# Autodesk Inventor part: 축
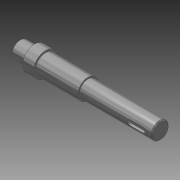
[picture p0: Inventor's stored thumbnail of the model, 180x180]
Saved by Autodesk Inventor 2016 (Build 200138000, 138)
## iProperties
Created: 2015-09
Part Number: 축
Material: 강철, 연강
Document SubType Name: Modeling
Designer: mduedu
Density: 7.86 g/cm^3
Mass: 263.424 g
Surface Area: 86.4309 cm^2
Volume: 33.5145 cm^3
Appearance: 반광택
Author: mduedu
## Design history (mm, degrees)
sketch "스케치1"
  geometry: L1 (-70, 0)-(70, 0); L2 (-70, 0)-(-70, 8.5); L3 (-70, 8.5)-(-55, 8.5); L4 (-55, 8.5)-(-55, 12); L5 (-55, 12)-(-44, 12); L6 (-44, 12)-(-44, 10); L7 (-44, 10)-(-2, 10); L8 (-2, 10)-(-2, 8.5); L9 (-2, 8.5)-(70, 8.5); L10 (70, 8.5)-(70, 0); 2 further points
  constraints: 20 end point, 5 parallel, 2 horizontal, 2 perpendicular, 1 coincident, 1 midpoint, 1 vertical
  dimensions: "d0" = 140 distance of L1.start L1.end; "d2" = 11 distance of L4.end L5.end; "d3" = 42 distance of L6.end L7.end; "d4" = 72 distance of L8.end L9.end; "d5" = 17 diameter of L3 L1; "d6" = 17 diameter of L9 L1; "d7" = 20 diameter of L7 L1; "d8" = 24 diameter of L5 L1
revolve "회전1" sketch "스케치1" stored, may be unused: angle "d9" = 90 deg
node "작업 평면1"
sketch "스케치2"
  geometry: L1 (13.5, 2.5)-(26.5, 2.5); L2 (26.5, -2.5)-(13.5, -2.5); L3 (13.5, 2.5)-(26.5, -2.5); L4 (26.5, 2.5)-(13.5, -2.5); L5 (36, -8.5)-(36, 8.5) reference; A1 r 2.5 centre (13.5, 0) between (13.5, 2.5) and (13.5, -2.5); A2 r 2.5 centre (26.5, 0) between (26.5, -2.5) and (26.5, 2.5); 2 further points
  constraints: 8 end point, 4 point on circle, 4 tangent, 2 centre point, 2 midpoint, 1 horizontal, 1 horizontal alignment, 1 parallel
  dimensions: "d10" = 18 dimension on A2 A1; "d12" = 7 distance edge to line of A2 L5; "d13" = 5 distance between parallel lines of L2 L1
extrude "돌출1" cut sketch "스케치2" distance "d14" = 3; taper "d15" = 0 deg
node "작업 평면2"
sketch "스케치4"
  geometry: L1 (7, -3)-(-9, -3); L2 (-9, 3)-(7, 3); L3 (-21, 10)-(-21, -10) reference; A1 r 3 centre (-9, 0) between (-9, 3) and (-9, -3); A2 r 3 centre (7, 0) between (7, -3) and (7, 3); 1 further point
  constraints: 4 end point, 4 point on circle, 4 tangent, 2 centre point, 1 horizontal, 1 horizontal alignment, 1 parallel
  dimensions: "d16" = 22 dimension on A1 A2; "d18" = 6 distance between parallel lines of L2 L1; "d19" = 9 distance edge to line of A1 L3
extrude "돌출2" cut sketch "스케치4" distance "d20" = 3.5; taper "d21" = 0 deg
sketch "스케치5"
  geometry: L1 (-2, 8.5)-(70, 8.5) reference; L2 (-2, -8.5)-(70, -8.5) reference; L3 (43, 8.5)-(43, -8.5); L4 (43, -6.5)-(41, -8.5); L5 (43, -8.5)-(41, -8.5); L6 (43, -8.5)-(43, -6.5); L7 (-2, -10)-(-2, 10) reference; 1 further point
  constraints: 8 end point, 4 point on line, 1 collinear, 1 perpendicular
  dimensions: "d22" = 4 diameter of L4.end L3; "d24" = 45 deg angle of L3 L4; "d26" = 45 distance between parallel lines of L3 L7
revolve "회전2" sketch "스케치5" stored, may be unused: angle "d27" = 90 deg
chamfer "모따기1" distance "d28" = 1; stored, may be unused: second distance "d29" = 2, angle "d30" = 45 deg
sketch "스케치6"
  geometry: L1 (43, -6.5)-(41, -8.5) reference; L2 (43, -6.5)-(45, -8.5) reference; 2 further points
  constraints: 1 coincident
node "솔리드1"
